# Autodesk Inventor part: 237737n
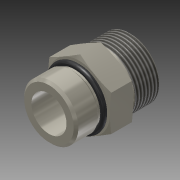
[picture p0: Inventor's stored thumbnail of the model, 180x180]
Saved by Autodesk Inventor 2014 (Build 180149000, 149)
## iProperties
Company: Autodesk, Inc.
Shininess: 64.0
Length Units: 11272
Angle Units: 11279
Time Units: 11290
Mass Units: 11286
Length Display Precision: 3
Angle Display Precision: 2
Compacted: True
Part Number: 237737n
Document SubType Name: Modeling
Created: 2003-10
Designer: Autodesk, Inc.
Material: Stainless Steel, Austenitic
Manufacturer: Standard
Standards Organization: Custom
Density: 8.03 g/cm^3
Mass: 275.548 g
Surface Area: 125.764 cm^2
Volume: 34.3148 cm^3
Appearance: Si Nitride (Polished)
Density: 0.0
Volumn: 0.0
Area: 0.0
PropertySet Name: Model Information
Control State: 0
Master: False
Checked Out: False
Author: Autodesk, Inc.
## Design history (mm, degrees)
feature "Base1"
sketch "Sketch1"
  geometry: L1 (0, 13.673)-(0, 17.976) reference; C1 r 1.537 at (16.726, 15.824); A1 r 1.524 centre (16.726, 15.824) between (16.726, 14.3) and (16.726, 17.348) reference
  constraints: 1 centre point, 1 coincident
  dimensions: "d1" = 3.0734 diameter of C1
revolve "Revolution1" sketch "Sketch1" stored, may be unused: angle "d0" = 90 deg
thread "Thread1" dims "d2" = 25.4, "d3" = 0
body "Solid1"
